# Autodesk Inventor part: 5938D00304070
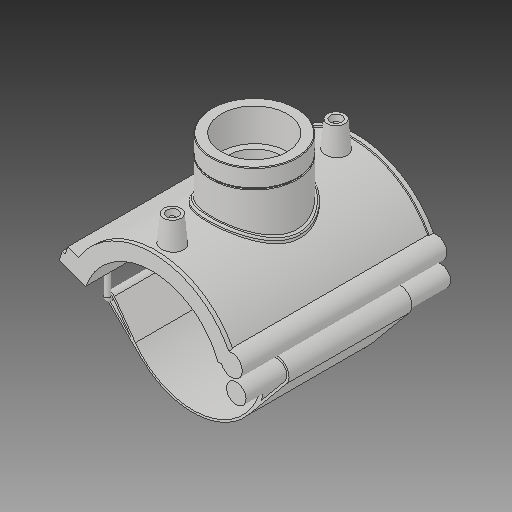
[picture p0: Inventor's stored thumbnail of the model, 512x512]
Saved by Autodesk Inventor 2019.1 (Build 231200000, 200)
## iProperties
Created: 2017-07
Part Number: 5938D00304070
Material: Generic
Description: PLASSON TRANSITION SADDLE 4''DIPS x 2"NPT
Document SubType Name: Modeling
Designer: KIM
Density: 1 g/cm^3
Appearance: Default
Author: KIM
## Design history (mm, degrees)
derived "5938D.ipt"
feature "Solid1::5938D.ipt"
tag "TaggingFeature1"
body "Solid1"
other parameters: "d_" = 121.3, "B_" = 165.1, "H_" = 46.736, "L_" = 176.022, "d_t" = 6, "G_" = 56.656, "d148" = 1.8195, "d160" = 1.8195, "d169" = 1.8195, "d192" = 4.852, "d0" = 121.3, "d1" = 145.56, "d2" = 412.75, "d3" = 30.325, "d4" = 176.022, "d5" = 0, "d40" = 75.6912, "d41" = 79.3184, "d43" = 0, "d45" = 0, "d47" = 119.516, "d48" = 73.6528, "d50" = 0, "d78" = 94.78, "d79" = 15, "d80" = 70.4088, "d82" = 5 deg, "d84" = 4, "d85" = 14, "d86" = 0, "d87" = 3, "d88" = 0, "d96" = 148.4712, "d97" = 3.52044, "d98" = 0, "d102" = 1.69968, "d103" = 56.656, "d104" = 28.0416, "d105" = 0, "d106" = 45.3248, "d108" = 0, "d109" = -15.57867, "d111" = 0.5, "d112" = 0.5, "d113" = 0, "d114" = 0.5, "d117" = 0.56656, "d120" = 140 deg, "d121" = 24.228, "d122" = 20 deg, "d123" = 582.24, "d124" = 87.336, "d126" = 0, "d143" = 124.939, "d145" = 18.66154, "d149" = 1.8195, "d150" = 20.52769, "d153" = 176.022, "d154" = 0, "d156" = 72.78, "d157" = 160 deg, "d159" = 4.852, "d161" = 1.8195, "d162" = 105.6132, "d163" = 0, "d164" = 60.65, "d167" = 12.13, "d168" = 71.00488, "d170" = 1.8195, "d172" = 0, "d173" = 1, "d175" = 60.65, "d176" = 20 deg, "d177" = 8.491, "d178" = 24.26, "d180" = 0, "d183" = 9.704, "d184" = 6.7928, "d185" = 57.20715, "d186" = 57.20715, "d187" = 72.78, "d188" = 7.278, "d189" = 8.491, "d190" = 0, "d191" = 87.336, "d193" = 4.852, "d194" = 2.48665, "d195" = 90 deg, "d197" = 0, "d199" = 0
